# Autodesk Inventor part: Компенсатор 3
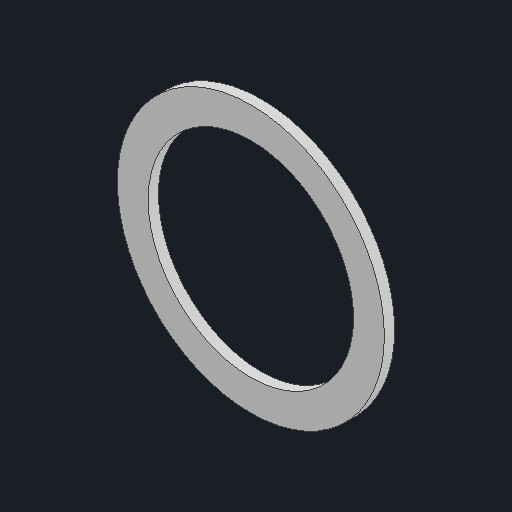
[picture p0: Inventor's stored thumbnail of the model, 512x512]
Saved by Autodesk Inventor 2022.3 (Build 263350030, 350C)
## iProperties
Created: 2020-09
Part Number: Компенсатор 3
Material: Типовые
Document SubType Name: Modeling
Designer: Карташов
Density: 1 g/cm^3
Appearance: По умолчанию
Title: D:\мои документы\Ирина\_WorldSkills\2020_09 ФНЧ\Module A\Участникам\GIVEN\Компенсатор 3.stp
Author: Дом
Sending System: Autodesk Inventor 2021
Preprocessor: ST-DEVELOPER v18.1
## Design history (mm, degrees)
feature "Твердое тело2"
node "Твердое тело1"
